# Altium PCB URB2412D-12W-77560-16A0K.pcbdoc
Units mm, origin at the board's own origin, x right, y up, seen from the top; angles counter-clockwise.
Board outline 75 x 35 mm, 2 copper layers (Top Layer, Bottom Layer), stack 0.78 mm thick; 59 components, 27 nets, 137 pads, 123 vias.
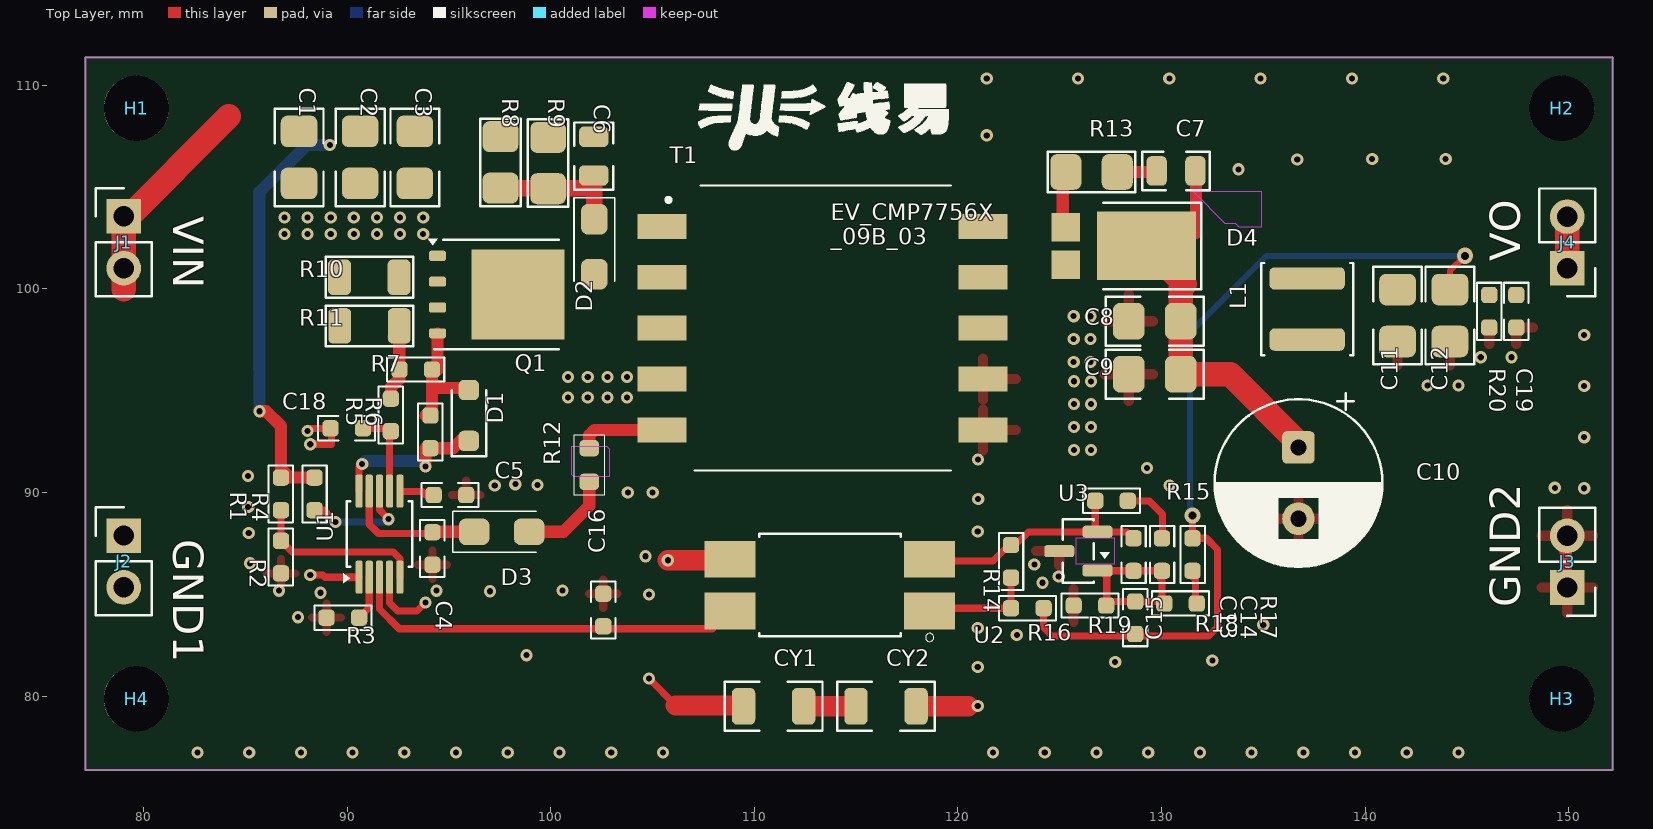
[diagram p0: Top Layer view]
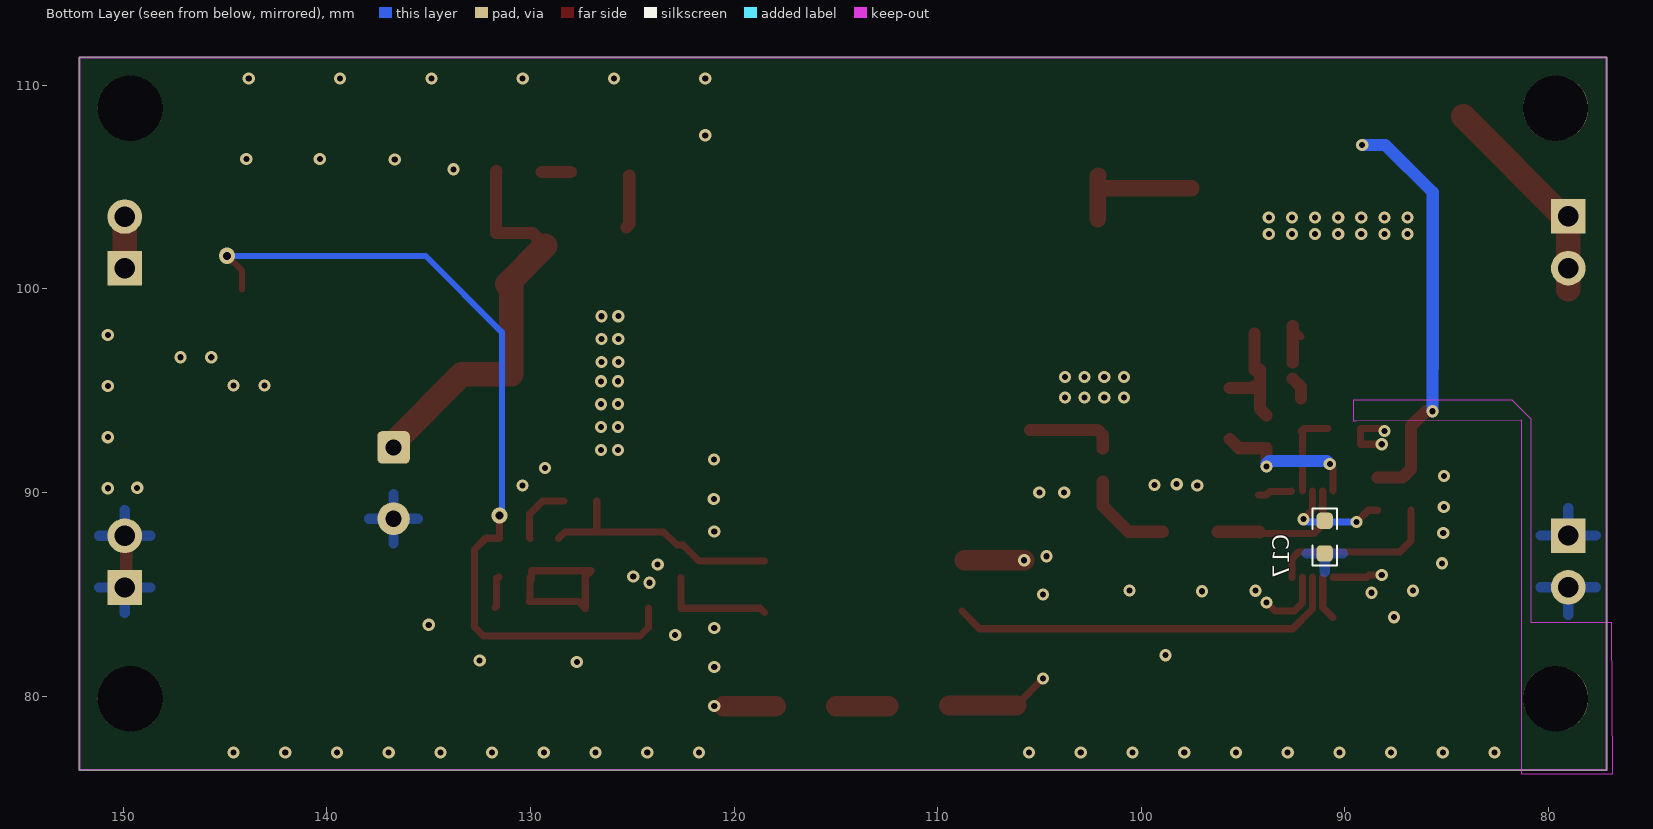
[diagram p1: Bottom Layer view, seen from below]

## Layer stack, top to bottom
Top Solder Mask Layer: solder mask 0.01, Dk 3.3
Top Layer: signal copper 0.035
Dielectric2: surface 0.71, FR4, Dk 4.5
Bottom Layer: signal copper 0.035
Bottom Solder Mask Layer: solder mask 0.01, Dk 3.3

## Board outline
77.15,111.37 152.15,111.37 152.15,76.37 77.15,76.37

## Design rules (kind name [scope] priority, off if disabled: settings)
BoardOutlineClearance copperThickness1oz [All] p0: genericclearance=0.254 ignorepadtopadclearanceinfootprint=FALSE except(0: Arc-SplitContinuation Track-SplitContinuation SMDPad-SplitContinuation THPad-SplitContinuation Via-SplitContinuation Fill-SplitContinuation Poly-SplitContinuation Region-SplitContinuation Text-SplitContinuation)
BoardOutlineClearance otherClearance [All] p0: genericclearance=0.254 ignorepadtopadclearanceinfootprint=FALSE except(0: Arc-SplitContinuation Track-SplitContinuation SMDPad-SplitContinuation THPad-SplitContinuation Via-SplitContinuation Fill-SplitContinuation Poly-SplitContinuation Region-SplitContinuation Text-SplitContinuation)
Clearance copperThickness1oz [All] p1: gap=0.178 ignorepadtopadclearanceinfootprint=FALSE
Clearance otherClearance [All] p1: gap=0.178 ignorepadtopadclearanceinfootprint=FALSE
DiffPairsRouting differentialPair [All] p1: maxuncoupledlength=10 minlimit=5 maxlimit=Infinity mostfreqgap=6 toplayer_minwidth=5 toplayer_prefwidth=100 toplayer_maxwidth=100 bottomlayer_minwidth=5 bottomlayer_prefwidth=100 bottomlayer_maxwidth=100
PasteMaskExpansion pasteMaskExpansion [All] p1: expansion=0
PlaneConnect innerPlane [All] p1: planeconnectstyle=Relief reliefexpansion=0.508 reliefentries=4 reliefconductorwidth=0.254 reliefairgap=0.254
PolygonConnect copper0 [All] p1: connectstyle=Direct reliefentries=4 reliefconductorwidth=10 polygonreliefangle="90 Angle" airgapwidth=10
PolygonConnect copper1 [All] p1: connectstyle=Relief reliefentries=4 reliefconductorwidth=19.685 polygonreliefangle="90 Angle" airgapwidth=15.748
PolygonConnect copper2 [All] p1: connectstyle=Relief reliefentries=4 reliefconductorwidth=15.748 polygonreliefangle="90 Angle" airgapwidth=11.811
PolygonConnect copper3 [All] p1: connectstyle=Relief reliefentries=4 reliefconductorwidth=19.685 polygonreliefangle="90 Angle" airgapwidth=19.685
RoutingVias viaSize [All] p1: viastyle="Through Hole" holewidth=24 minholewidth=11.811 maxholewidth=393.7 width=24 minwidth=11.811 maxwidth=393.7
SolderMaskExpansion solderMaskExpansion [All] p1: useseparateexpansions=TRUE expansion=2 expansionbottom=2
Width copperThickness1oz [All] p1: maxlimit=100 minlimit=5 preferedwidth=10

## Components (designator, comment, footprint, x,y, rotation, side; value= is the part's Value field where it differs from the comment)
C1 "Coileasy library_C" MYLibrary:C1206A 87.64,106.455 r90 top
C2 "Coileasy library_C" MYLibrary:C1206A 90.64,106.455 r90 top
C3 "Coileasy library_C" MYLibrary:C1206A 93.33,106.455 r90 top
C4 "Coileasy library_C" MYLibrary:C0603 94.189,87.253 r90 top
C5 "Coileasy library_C" MYLibrary:C0603 95.05,89.878 r180 top
C6 "Coileasy library_C" MYLibrary:C0805 102.11,106.52 r90 top
C7 "Coileasy library_C" MYLibrary:C0805 130.71,105.79 r180 top
C8 "Coileasy library_C" MYLibrary:C1206A 129.663,98.41 r0 top
C9 "Coileasy library_C" MYLibrary:C1206A 129.663,95.81 r0 top
C10 "Device_C_Polarized" Capacitor_THT:CP_Radial_D8.0mm_P3.50mm 136.72,92.213 r270 top
C11 "Coileasy library_C" MYLibrary:C1206A 141.585,98.69 r90 top
C12 "Coileasy library_C" MYLibrary:C1206A 144.16,98.69 r90 top
C13 "Coileasy library_C" MYLibrary:C0603 128.62,86.95 r270 top
C14 "Coileasy library_C" MYLibrary:C0603 130.02,86.95 r270 top
C15 "Coileasy library_C" MYLibrary:C0603 128.7,83.85 r270 top
C16 "Coileasy library_C" MYLibrary:C0603 102.58,84.23 r270 top
C17 "Coileasy library_C" MYLibrary:C0603 90.99,87.808 r270 bottom
C18 "Coileasy library_C" MYLibrary:C0603 89.98,93.15 r180 top
C19 "Coileasy library_C" MYLibrary:C0603 147.42,98.9 r90 top
CY1 "Coileasy library_C" MYLibrary:C1206 110.945,79.5 r180 top
CY2 "Coileasy library_C" MYLibrary:C1206 116.465,79.5 r180 top
D1 "Coileasy library_D" Diode_SMD:D_SOD-323_HandSoldering 95.98,93.782 r90 top
D2 "Coileasy library_D" MYLibrary:SOD-123-323 102.14,102.07 r270 top
D3 "Coileasy library_D" MYLibrary:SOD-123-323 97.589,88.07 r0 top
D4 "Device_D" Diode_SMD:D_PowerDI-5 128.142,102.11 r180 top
H1 "Mechanical_MountingHole" MountingHole:MountingHole_3.2mm_M3 79.65,108.87 r0 top
H2 "Mechanical_MountingHole" MountingHole:MountingHole_3.2mm_M3 149.65,108.87 r0 top
H3 "Mechanical_MountingHole" MountingHole:MountingHole_3.2mm_M3 149.65,79.87 r0 top
H4 "Mechanical_MountingHole" MountingHole:MountingHole_3.2mm_M3 79.65,79.87 r0 top
J1 "Coileasy library_Conn_01x02" Connector_PinHeader_2.54mm:PinHeader_1x02_P2.54mm_Vertical 79.03,103.56 r0 top
J2 "Coileasy library_Conn_01x02" Connector_PinHeader_2.54mm:PinHeader_1x02_P2.54mm_Vertical 79.03,87.885 r0 top
J3 "Coileasy library_Conn_01x02" Connector_PinHeader_2.54mm:PinHeader_1x02_P2.54mm_Vertical 149.92,85.335 r180 top
J4 "Coileasy library_Conn_01x02" Connector_PinHeader_2.54mm:PinHeader_1x02_P2.54mm_Vertical 149.92,101.01 r180 top
L1 "Device_L" Inductor_SMD:L_APV_ANR4018 137.15,99.01 r90 top
Q1 "Transistor_FET_BSC026N08NS5" Package_TO_SOT_SMD:TDSON-8-1 97.34,99.72 r0 top
R1 "Coileasy library_R" MYLibrary:R0603 86.75,89.93 r270 top
R2 "Coileasy library_R" MYLibrary:R0603 86.75,86.83 r270 top
R3 "Coileasy library_R" MYLibrary:R0603 89.789,83.852 r0 top
R4 "Coileasy library_R" MYLibrary:R0603 88.4,89.93 r90 top
R5 "Coileasy library_R" MYLibrary:R0603 92.15,93.81 r270 top
R6 "Coileasy library_R" MYLibrary:R0603 94.09,92.978 r270 top
R7 "Coileasy library_R" MYLibrary:R0603 93.37,96.04 r180 top
R8 "Coileasy library_R" MYLibrary:R1206A 97.53,106.21 r90 top
R9 "Coileasy library_R" MYLibrary:R1206A 99.87,106.18 r90 top
R10 "Coileasy library_R" MYLibrary:R1206 91.09,100.57 r0 top
R11 "Coileasy library_R" MYLibrary:R1206 91.1,98.18 r0 top
R12 "Coileasy library_R" coileasy:R_0603 101.89,91.35 r90 top
R13 "Coileasy library_R" MYLibrary:R1206A 126.56,105.74 r0 top
R14 "Coileasy library_R" MYLibrary:R0603 122.605,86.618 r270 top
R15 "Coileasy library_R" MYLibrary:R0603 127.54,89.59 r180 top
R16 "Coileasy library_R" MYLibrary:R0603 123.405,84.317 r180 top
R17 "Coileasy library_R" MYLibrary:R0603 131.52,86.95 r90 top
R18 "Coileasy library_R" MYLibrary:R0603 130.93,84.55 r0 top
R19 "Coileasy library_R" MYLibrary:R0603 126.48,84.45 r0 top
R20 "Coileasy library_R" MYLibrary:R0603 146.09,98.9 r90 top
T1 "MYLibrary_CMB4+4" MYLibrary:EP13 113.35,98.07 r0 top
U1 "MYLibrary_CMP7756X" Package_SO:MSOP-10_3x3mm_P0.5mm 91.589,87.953 r90 top
U2 "PC817B__Slkor_PC817B__Slkor" kicad_community_lib:PC817B__Slkor 113.61,85.37 r180 top
U3 "Coileasy library_CJ431" Package_TO_SOT_SMD:SOT-23 125.913,87.12 r180 top

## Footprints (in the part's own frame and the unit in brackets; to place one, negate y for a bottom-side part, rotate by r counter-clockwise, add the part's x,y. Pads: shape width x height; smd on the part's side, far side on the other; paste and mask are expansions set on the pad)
Capacitor_THT:CP_Radial_D8.0mm_P3.50mm [mm]
  rrect31% 1.6x1.6 hole 0.8: 1(0,0)
  round 1.6 hole 0.8: 2(3.5,0)
  silkscreen extent -2.66,-4.12 5.87,4.12
coileasy:R_0603 [mm]
  rrect50% 0.8x0.95 smd: 1(-0.825,0) 2(0.825,0)
  silkscreen extent -1.48,-0.73 1.48,0.73
Connector_PinHeader_2.54mm:PinHeader_1x02_P2.54mm_Vertical [mm]
  rect 1.7x1.7 hole 1: 1(0,0)
  round 1.7 hole 1: 2(0,-2.54)
  silkscreen extent -1.38,-3.92 1.38,1.38
Diode_SMD:D_PowerDI-5 [mm]
  rect 4.86x3.36 smd: 1(-1.12,0)
  rect 1.4x1.39 smd: 2(2.862,-0.92) 2(2.862,0.92)
  silkscreen extent -3.81,-2.12 1,2.12
Diode_SMD:D_SOD-323_HandSoldering [mm]
  rrect50% 1x1 smd: 1(-1.25,0) 2(1.25,0)
  silkscreen extent -2.01,-0.85 1.25,0.85
Inductor_SMD:L_APV_ANR4018 [mm]
  rrect45% 1.1x3.7 smd: 1(-1.5,0) 2(1.5,0)
  silkscreen extent -2.26,-2.26 2.26,2.26
kicad_community_lib:PC817B__Slkor [mm]
  rect 2.5x1.8 smd: 1(-5,1.19) 2(-5,-1.35) 3(4.8,-1.35) 4(4.8,1.19)
  silkscreen extent -5.2,-2.6 3.37,2.69
MountingHole:MountingHole_3.2mm_M3 [mm]
  round 3.2 hole 3.2 unplated: ""(0,0)
MYLibrary:C0603 [mm]
  rrect50% 0.8x0.8 smd: 1(-0.8,0) 2(0.8,0)
  silkscreen extent -1.4,-0.6 1.4,0.6
MYLibrary:C0805 [mm]
  rrect50% 1x1.45 smd: 1(-0.95,0) 2(0.95,0)
  silkscreen extent -1.65,-0.95 1.65,0.96
MYLibrary:C1206 [mm]
  rrect43% 1.15x1.8 smd: 1(-1.475,0) 2(1.475,0)
  silkscreen extent -2.4,-1.2 2.4,1.2
MYLibrary:C1206A [mm]
  rrect43% 1.55x1.8 smd: 1(-1.275,0) 2(1.275,0)
  silkscreen extent -2.4,-1.2 2.4,1.2
MYLibrary:EP13 [mm]
  rect 2.4x1.22 smd: 1(-7.88,5) 2(-7.88,2.5) 3(-7.88,0) 4(-7.88,-2.5) 5(-7.88,-5) 6(7.88,-5) 7(7.88,-2.5) 8(7.88,0) 9(7.88,2.5) 10(7.88,5)
  silkscreen extent -7.62,-7 6.3,7
MYLibrary:R0603 [mm]
  rrect50% 0.8x0.8 smd: 1(-0.8,0) 2(0.8,0)
  silkscreen extent -1.4,-0.6 1.4,0.6
MYLibrary:R1206 [mm]
  rrect44% 1.125x1.75 smd: 1(-1.463,0) 2(1.462,0)
  silkscreen extent -2.15,-1 2.15,1
MYLibrary:R1206A [mm]
  rrect44% 1.525x1.75 smd: 1(-1.262,0) 2(1.262,0)
  silkscreen extent -2.15,-1 2.15,1
MYLibrary:SOD-123-323 [mm]
  rrect50% 1.5x1.3 smd: 1(-1.35,0) 2(1.35,0)
  silkscreen extent -2.4,-1 1.7,1
Package_SO:MSOP-10_3x3mm_P0.5mm [mm]
  rrect50% 1.625x0.35 smd: 1(-2.113,1) 2(-2.113,0.5) 3(-2.113,0) 4(-2.113,-0.5) 5(-2.113,-1) 6(2.113,-1) 7(2.113,-0.5) 8(2.113,0) 9(2.113,0.5) 10(2.113,1)
  silkscreen extent -2.4,-1.61 1.61,1.77
Package_TO_SOT_SMD:SOT-23 [mm]
  rrect50% 1.475x0.6 smd: 1(-0.937,0.95) 2(-0.937,-0.95) 3(0.938,0)
  silkscreen extent -1.54,-1.56 0.76,1.56
Package_TO_SOT_SMD:TDSON-8-1 [mm]
  rrect50% 0.85x0.5 smd: 1(-2.9,1.905) 2(-2.9,0.635) 3(-2.9,-0.635) 4(-2.9,-1.905)
  rect 4.55x4.41 smd: 5(1.05,0)
  silkscreen extent -3.37,-2.69 3.06,2.75

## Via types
v1: diameter 0.6, hole 0.3, Top Layer to Bottom Layer, 121 vias
v2: diameter 0.8, hole 0.4, Top Layer to Bottom Layer, 2 vias

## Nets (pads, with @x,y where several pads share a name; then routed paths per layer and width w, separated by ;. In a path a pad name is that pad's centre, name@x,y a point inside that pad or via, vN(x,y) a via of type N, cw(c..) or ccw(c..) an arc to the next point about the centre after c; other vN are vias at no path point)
$1N4: C7.1 C8.2 C9.2 C10.1 D4.1 L1.1 | length 20.3
  Top Layer w0.6: D4.1 129.893,102.74 131.69,102.74 131.69,105.76 C7.1
  Top Layer w1.2: D4.1 131.137,100.235 130.938,100.035 C8.2 C9.2 133.36,95.81 136.72,92.45 C10.1
$1N5: C13.2 C14.2 C15.1 R18.1 R19.2 U3.1 | length 9.5
  Top Layer w0.35: U3.1@127.015,86.158 127.305,85.868 127.305,84.317 127.637,84.65 C15.1 130.073,84.65 130.02,84.703 130.02,85.827 129.943,85.75 129.943,86.158 U3.1@127.015,86.158
$1N10: C13.1 R14.1 R15.2 U2.2 U3.2 | length 12.4
  Top Layer w0.35: U2.2@118.51,86.64 121.72,86.64 122.498,87.418 R14.1 122.805,87.418 123.455,88.067 126.85,88.067 128.302,88.067 C13.1 ; R15.2 126.74,88.18 U3.2
$1N11: D4.2 R13.1 T1.9 T1.10 | length 2.6
  Top Layer w0.6: R13.1@125.14,105.57 125.14,103.17 D4.2@125.281,103.03
$1N12: D2.2 Q1.5 T1.3
$1N13: R14.2 R16.2 U2.1 | length 5.7
  Top Layer w0.35: U2.1@118.51,84.1 118.727,84.317 R16.2 R14.2
$1N18: D1.2 Q1.4 R6.1 R7.1 | length 5.9
  Top Layer w0.6: R6.1@93.85,93.778 94.17,94.098 94.17,95.307 ; R7.1 94.17,95.307 ; 94.44,95.218 94.35,95.128 ; R7.1@94.44,96.01 Q1.4 ; D1.2@95.65,95.128 94.35,95.128 ; 94.17,95.307 94.35,95.128
$1N19: C6.1 D2.1 R8.1 R9.1 | length 6.8
  Top Layer w0.8: R8.1 102.063,104.948 102.14,104.87 ; C6.1 102.14,105.54 102.14,104.87 ; D2.1 102.14,104.87
$1N23: D1.1 R6.2 U1.10 | length 7.7
  Top Layer w0.35: U1.10 90.589,91.252 v1(90.739,91.402)
  Top Layer w0.6: v1(93.85,91.278) 93.85,92.177 95.2,92.177 D1.1@95.65,92.628
  Bottom Layer w0.6: v1(90.739,91.402) 90.889,91.553 93.714,91.553 93.85,91.417 v1(93.85,91.278)
$1N26: C14.1 R15.1 | length 3.2
  Top Layer w0.35: R15.1 129.39,89.59 130.05,88.93 130.05,87.78 C14.1
$1N30: R12.2 T1.5 | length 4.3
  Top Layer w0.6: R12.2 101.89,92.812 102.147,93.07 T1.5
$1N31: R17.1 R18.2 | length 1.5
  Top Layer w0.35: R17.1@131.54,85.84 R17.1@131.55,85.83 ; R17.1@131.67,85.8 131.67,84.41 R18.2@131.73,84.35
$1N33: CY1.1 CY2.2 | length 2.6
  Top Layer w1: CY1.1 CY2.2
$1N36: C7.2 R13.2 | length 1.4
  Top Layer w0.6: R13.2@128.022,105.74 C7.2@129.458,105.74
$1N45: D3.2 R12.1 | length 4.7
  Top Layer w0.6: D3.2 100.62,88.07 101.89,89.34 R12.1
COMP: C16.2 U1.3 U2.4 | length 19.5
  Top Layer w0.35: U1.3 91.589,84.277 92.559,83.308 107.938,83.308 U2.4
CS: C18.1 R5.2 U1.7 | length 4.3
  Top Layer w0.35: C18.1@90.84,93.15 92.01,93.15 R5.2 92.089,92.949 U1.7
EN: R1.2 R2.1 U1.5 | length 8.6
  Top Layer w0.35: R1.2 R2.1 87.303,87.077 92.264,87.077 92.589,86.753 U1.5
GND1: C1.1 C2.1 C3.1 C4.1 C5.1 C16.1 C17.2 C18.2 CY1.2 J2.1 J2.2 R2.2 R3.1 R10.1 R11.1 T1.4 U1.1 U1.4 U2.3 | length 17
  Top Layer w0.35: v1(88.06,93.02) 88.19,93.15 C18.2 ; v1(88.19,85.95) 88.817,85.95 88.927,85.84 U1.1 ; v1(88.19,92.37) 89.23,92.37 89.24,92.38 C18.2@89.24,93.15 ; U1.4 92.089,84.578 92.489,84.177 93.427,84.177 v1(93.85,84.6) ; v1(104.82,80.86) 106.14,79.54 ; CY1.2@109.43,79.54 CY1.2
  Top Layer w0.6: U2.3@108.68,86.67 U2.3@108.71,86.64
  Top Layer w1: v1(105.75,86.67) U2.3@108.68,86.67 ; 106.14,79.54 CY1.2@109.43,79.54
  other v1: 82.65,77.23 85.19,77.23 87.73,77.23 90.27,77.23 92.81,77.23 95.35,77.23 97.89,77.23 100.43,77.23 102.97,77.23 105.51,77.23 98.81,82.01 87.589,83.878 104.83,84.99 88.689,85.078 97.02,85.15 86.65,85.178 94.389,85.178 100.58,85.19 85.23,86.52 104.65,86.87 85.17,88.01 85.14,89.29 103.785,90 105.005,90 97.25,90.34 99.35,90.37 98.26,90.41 85.13,90.81 100.85,94.67 101.817,94.67 102.783,94.67 103.75,94.67 100.85,95.67 101.817,95.67 102.783,95.67 103.75,95.67 86.924,102.69 88.059,102.69 89.194,102.69 90.329,102.69 91.464,102.69 92.599,102.69 93.734,102.69 86.924,103.5 88.059,103.5 89.194,103.5 90.329,103.5 91.464,103.5 92.599,103.5 93.734,103.5
GND2: C8.1 C9.1 C10.2 C11.1 C12.1 C19.1 CY2.1 J3.1 J3.2 R19.1 R20.1 T1.6 T1.7 U3.3 | length 5.5
  Top Layer w0.35: 120.51,79.5 120.54,79.47 120.59,79.52 v1@120.86,79.52
  Top Layer w0.6: J3.1@149.85,85.895 J3.2@149.85,88.435
  Top Layer w1: CY2.1 120.41,79.5 120.51,79.5
  other v1: 121.72,77.23 124.26,77.23 126.8,77.23 129.34,77.23 131.88,77.23 134.42,77.23 136.96,77.23 139.5,77.23 142.04,77.23 144.58,77.23 120.97,79.52 120.97,81.43 127.72,81.68 132.49,81.75 122.89,83 120.97,83.34 134.99,83.5 124.15,85.57 124.95,85.87 123.75,86.47 120.97,88.09 120.99,89.68 149.31,90.23 150.75,90.21 130.39,90.34 129.28,91.2 120.98,91.62 125.702,92.093 126.533,92.09 150.75,92.717 125.702,93.217 126.533,93.213 125.702,94.34 126.533,94.337 150.75,95.223 143.06,95.25 144.58,95.25 125.702,95.463 126.533,95.46 125.68,96.413 126.51,96.41 145.67,96.64 147.18,96.64 125.68,97.537 126.51,97.533 150.75,97.73 125.68,98.66 126.51,98.657 133.77,105.87 136.66,106.35 140.34,106.38 143.95,106.38 121.41,107.54 121.41,110.33 125.894,110.33 130.378,110.33 134.862,110.33 139.346,110.33 143.83,110.33
IS: Q1.1 Q1.2 Q1.3 R5.1 R7.2 R10.2 R11.2 | length 3.5
  Top Layer w0.35: R11.2@92.15,97.668 R11.2@92.562,98.08
  Top Layer w0.6: R5.1 92.15,95.178 92.562,95.59 ; R7.2@92.562,96.382 92.562,98.08 R11.2
RT: R3.2 U1.2 | length 2.2
  Top Layer w0.35: R3.2 91.089,84.353 U1.2
SS: C5.2 U1.6 | length 1.7
  Top Layer w0.35: U1.6@92.614,90.065 92.614,90.052 93.689,90.052 93.864,89.878 C5.2
VCC: C4.2 D3.1 U1.9 | length 6.9
  Top Layer w0.35: U1.9 91.089,88.438 91.55,87.977 C4.2@94.114,87.977
  Top Layer w0.6: C4.2 94.207,88.07 D3.1
VIN: C1.2 C2.2 C3.2 C6.2 J1.1 J1.2 R1.1 R4.2 R8.2 R9.2 T1.1 | length 31.2
  Top Layer w0.35: R4.2 R4.2@88.4,90.863
  Top Layer w0.6: v1(85.7,93.99) 86.02,93.99 86.75,93.26 86.75,91.153 87.173,90.73 88.267,90.73 R4.2
  Top Layer w1.2: 79.03,99.98 J1.2 79.03,103.304 84.196,108.47
  Bottom Layer w0.6: v1(85.7,93.99) 85.7,96.09 85.69,96.1 85.69,104.74 88.02,107.07 v1(89.15,107.07)
VIN1: C17.1 R4.1 U1.8 | length 5.5
  Top Layer w0.35: R4.1 88.853,89.13 v1(89.43,88.553) ; U1.8 91.589,89.153 91.939,88.802 91.939,88.788 v1(92.037,88.69)
  Bottom Layer w0.35: v1(89.43,88.553) 91.9,88.553 v1(92.037,88.69)
VO: C11.2 C12.2 C15.2 C19.2 J4.1 J4.2 L1.2 R16.1 R17.2 R20.2 | length 44.8
  Top Layer w0.3: C12.2 144.16,100.88 v2(144.9,101.62)
  Top Layer w0.35: R16.1 124.205,83.365 124.62,82.95 132.295,82.95 132.74,83.395 132.74,87.2 132.19,87.75 R17.2 v2(131.52,88.87)
  Top Layer w1.2: J4.1 J4.2
  Bottom Layer w0.3: v2(131.52,88.87) 131.4,88.99 131.4,97.87 135.15,101.62 v2(144.9,101.62)
pads on no net: H1. H2. H3. H4. T1.2 T1.8

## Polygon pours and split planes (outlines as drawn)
VO on Top Layer (solid, remove dead copper, pour order 2): 134.885,99.69 134.885,103.93 135.995,105.04 151.28,105.04 151.38,104.94 151.38,99.16 151.24,99.02 134.81,99.02 134.81,99.615
$1N12 on Top Layer (solid, remove dead copper, pour order 4): 106.67,97.46 96.115,97.46 96.115,101.925 103.195,101.925 103.55,101.57 103.55,99.4 103.77,99.18 106.67,99.18
$1N4 on Top Layer (solid, remove dead copper, pour order 6): 126.832,103.77 132.55,103.77 133.2,103.12 133.2,98.73 133.66,98.27 139.935,98.27 139.92,91.39 139.89,91.39 137.007,91.393 136.905,91.29 131.113,91.29 130.163,92.24 130.163,100.258 130.01,100.41 127.293,100.41 126.832,100.87
GND1 on Top Layer (solid, remove dead copper, pour order 8): 81.334,91.582 106.75,91.57 106.75,76.36 81.33,76.36 81.33,89.27
IS on Top Layer (solid, remove dead copper, pour order 10): 92.012,101.875 94.867,101.875 94.867,97.015 92.012,97.015
VIN on Top Layer (solid, remove dead copper, pour order 12): 77.65,99.07 77.65,106.85 80.508,106.85 84.268,110.65 106.15,110.65 106.7,110.1 106.7,102.41 103.58,102.41 103.58,106.02 102.91,106.69 86.5,106.69 82.811,103.001 82.803,100.058 81.815,99.07
GND1 on Top Layer (solid, remove dead copper, pour order 14): 87.65,94.23 89.58,94.23 89.58,92.09 87.65,92.09
$1N11 on Top Layer (solid, remove dead copper, pour order 16): 120.03,100.011 120.03,105.97 125.783,105.97 125.968,105.785 125.968,99.97
GND1 on Top Layer (solid, remove dead copper, pour order 18): 100.35,96.27 106.67,96.27 106.67,94.26 100.35,94.26
GND1 on Top Layer (solid, remove dead copper, pour order 20): 76.89,98.16 82.36,98.16 83.86,99.66 83.86,103.14 86.66,105.94 94.2,105.94 94.33,105.94 94.33,102.15 94.01,101.83 90.5,101.83 90.18,101.51 90.18,94.93 82.18,94.93 80.84,93.59 80.84,90.34 80.84,83.81 76.89,83.81
GND1 on Bottom Layer (solid, remove dead copper, pour order 44): 77.21,111.48 106.75,111.48 106.75,76.43 77.17,76.43 77.17,111.46 77.2,111.49
GND2 on Top Layer (solid, remove dead copper, pour order 24): 119.87,76.365 119.87,111.355 152.16,111.355 152.16,76.365
GND2 on Bottom Layer (solid, remove dead copper, pour order 48): 119.87,76.365 119.87,111.355 152.16,111.355 152.16,76.365

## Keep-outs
Top Layer:
  region: 131.55,104.79 134.885,104.79 134.885,103.03 133.81,103.03 133.63,103.21 133.13,103.21
  region: 101.015,92.25 101.015,90.9 101.125,90.79 102.9,90.79 102.9,92.115 102.765,92.25
  region: 125.805,87.768 127.68,87.768 127.68,86.468 125.805,86.468
Bottom Layer:
  region: 81.33,76.2 76.85,76.2 76.89,83.61 80.84,83.61 80.84,93.59 81.77,94.52 89.59,94.52 89.59,93.521 89.439,93.521 81.347,93.57 81.338,93.579 81.33,93.571
Board Outline Layer:
  the board outline again, w0.1

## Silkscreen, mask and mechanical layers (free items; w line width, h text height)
Top Silkscreen Layer:
  drawing of 9 lines, arcs and shapes, not listed
  text "VIN" at 81.458,103.57 h1.5 r270
  text "EV_CMP7756X / _09B_03" at 113.75,102.17 h0.8
  text "VO" at 147.612,101.363 h1.5 r90
  text "GND1" at 81.458,87.706 h1.5 r270
  text "GND2" at 147.612,84.376 h1.5 r90
User.Eco1:
